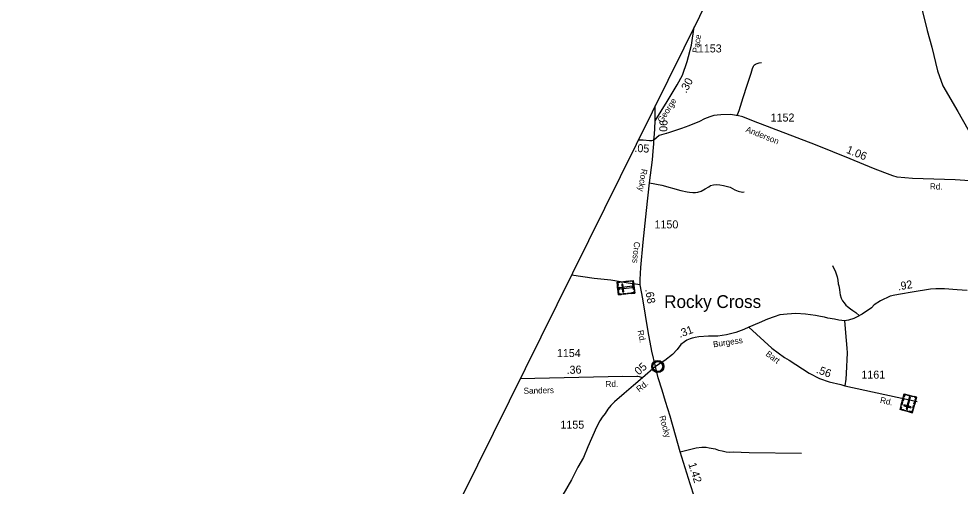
# Model space of a CAD drawing. Extents: x 2220236 to 2384410, y 720751 to 894131.
# Drawn here: x 2220576 to 2235281, y 768138 to 775435 of the extents above; entities that cross this region are included whole.
import ezdxf

# ---------------------------------------------------------------- set-up
doc = ezdxf.new("R2010")
doc.units = 0
doc.layers.add('Default', color=7, linetype='Continuous')

msp = doc.modelspace()

# ---------------------------------------------------------------- linework, layer by layer
at = {"layer": 'Default'}
for p, q in [((2230516, 773844), (2230516, 774074)), ((2230520, 770009), (2230316, 769832))]:
    msp.add_line(p, q, dxfattribs=at)
for points in [[(2293118, 894131), (2291904, 891776), (2258822, 829665), (2255410, 823324), (2242089, 797599), (2231460, 775981), (2225011, 762953), (2220576, 753519)], [(2234647, 775741), (2234764, 775250), (2234839, 774993), (2234924, 774625), (2235009, 774391), (2235244, 773990), (2235402, 773711), (2235753, 773038), (2235850, 772874)], [(2230516, 773844), (2230705, 774144), (2230862, 774403), (2230945, 774553), (2231016, 774771), (2231083, 775022), (2231127, 775308)], [(2231799, 773924), (2231829, 774005), (2231893, 774209), (2231955, 774397), (2232017, 774587), (2232036, 774659), (2232050, 774694), (2232059, 774707), (2232069, 774717), (2232085, 774725), (2232112, 774736), (2232139, 774746), (2232176, 774752)], [(2235432, 772907), (2235201, 772920), (2234535, 772942), (2234295, 772964), (2234227, 772985), (2234102, 773031), (2233926, 773099), (2233562, 773248), (2233021, 773465), (2232050, 773838), (2231887, 773906), (2231799, 773924), (2231782, 773928), (2231698, 773940), (2231542, 773937), (2231484, 773933), (2231430, 773923), (2231372, 773906), (2231288, 773874), (2231211, 773834), (2231043, 773763), (2230926, 773723), (2230832, 773692), (2230723, 773656), (2230579, 773614), (2230496, 773541)], [(2230496, 773541), (2230505, 773636), (2230512, 773720), (2230516, 773844)], [(2230496, 773541), (2230461, 773532), (2230427, 773532), (2230328, 773538), (2230251, 773540)], [(2230520, 770009), (2230466, 770246), (2230407, 770554), (2230321, 771064), (2230284, 771284), (2230284, 771363), (2230292, 771551), (2230331, 771947), (2230380, 772442), (2230425, 772876), (2230473, 773233), (2230484, 773370), (2230494, 773483), (2230496, 773541)], [(2230425, 772876), (2230620, 772839), (2230915, 772757), (2231016, 772735), (2231054, 772730), (2231102, 772724), (2231147, 772724), (2231185, 772728), (2231234, 772744), (2231296, 772780), (2231354, 772811), (2231381, 772832), (2231428, 772844), (2231482, 772846), (2231525, 772844), (2231586, 772834), (2231688, 772808), (2231763, 772763), (2231813, 772742), (2231880, 772730), (2231906, 772735)], [(2233288, 771583), (2233331, 771487), (2233360, 771409), (2233372, 771353), (2233376, 771297), (2233385, 771265), (2233395, 771210), (2233400, 771158), (2233406, 771124), (2233424, 771072), (2233443, 771034), (2233467, 771000), (2233497, 770965), (2233519, 770943), (2233566, 770905), (2233604, 770879), (2233652, 770852), (2233707, 770799)], [(2230284, 771284), (2230092, 771309), (2229822, 771353), (2229562, 771383), (2229208, 771432)], [(2235392, 771193), (2235234, 771204), (2235037, 771217), (2234899, 771218), (2234815, 771216), (2234532, 771166), (2234347, 771136), (2234259, 771119), (2234189, 771103), (2234035, 771034), (2233939, 770970), (2233894, 770925), (2233750, 770826), (2233673, 770782), (2233617, 770755), (2233537, 770730), (2233472, 770721), (2233432, 770725), (2233387, 770730), (2233316, 770744), (2233212, 770763), (2233160, 770775), (2233099, 770786), (2233023, 770803), (2232863, 770826), (2232714, 770832), (2232578, 770826), (2232465, 770812), (2232377, 770781), (2232270, 770744), (2232143, 770691), (2231978, 770620)], [(2233472, 770721), (2233498, 770411), (2233510, 770295), (2233513, 770220), (2233498, 769899), (2233493, 769811), (2233478, 769707)], [(2231978, 770620), (2231900, 770586), (2231777, 770537), (2231629, 770500), (2231494, 770479), (2231349, 770479), (2231196, 770468), (2231142, 770458), (2231120, 770454), (2231094, 770449), (2231061, 770439), (2231038, 770430), (2231010, 770416), (2230972, 770392), (2230917, 770348), (2230859, 770271), (2230785, 770196), (2230669, 770101), (2230520, 770009)], [(2231978, 770620), (2232099, 770513), (2232340, 770295), (2232534, 770145), (2232611, 770106), (2232922, 769904), (2233085, 769821), (2233234, 769766), (2233417, 769725), (2233478, 769707), (2234607, 769462)], [(2232001, 766033), (2231986, 766056), (2231957, 766104), (2231915, 766158), (2231869, 766209), (2231744, 766320), (2231622, 766441), (2231556, 766540), (2231515, 766658), (2231495, 766738), (2231447, 766978), (2231378, 767299), (2231337, 767427), (2231327, 767474), (2231206, 767744), (2231128, 767969), (2231063, 768174), (2230907, 768676), (2230835, 768936), (2230749, 769232), (2230675, 769462), (2230626, 769636), (2230564, 769829), (2230520, 770009)], [(2230316, 769832), (2230270, 769846), (2230013, 769850), (2228406, 769812)], [(2230316, 769832), (2230180, 769712), (2230034, 769585), (2229881, 769454), (2229826, 769399), (2229778, 769339), (2229737, 769275), (2229687, 769214), (2229654, 769158), (2229600, 769060), (2229463, 768753), (2229394, 768588), (2229310, 768434), (2229209, 768235), (2229075, 768002)], [(2230907, 768676), (2231158, 768736), (2231246, 768747), (2231314, 768748), (2231360, 768736), (2231452, 768721), (2231506, 768703), (2231563, 768688), (2231627, 768672), (2231677, 768671), (2231735, 768673), (2231987, 768665), (2232800, 768656)]]:
    msp.add_lwpolyline(points, dxfattribs=at)
for points in [[(2229944, 771124), (2229921, 771322), (2230174, 771351), (2230197, 771153)], [(2229964, 771327), (2229966, 771316), (2229934, 771312), (2229938, 771272), (2229927, 771271), (2229921, 771322)], [(2230007, 771173), (2230025, 771175), (2230012, 771292), (2229993, 771290)], [(2230038, 771324), (2229995, 771319), (2229994, 771331), (2230037, 771335)], [(2230104, 771332), (2230061, 771327), (2230059, 771338), (2230102, 771343)], [(2230178, 771318), (2230167, 771317), (2230164, 771339), (2230124, 771334), (2230123, 771345), (2230174, 771351)], [(2230179, 771209), (2230169, 771293), (2230181, 771295), (2230190, 771210)], [(2229935, 771198), (2229929, 771250), (2229941, 771251), (2229947, 771199)], [(2229987, 771129), (2229985, 771141), (2229953, 771137), (2229949, 771177), (2229938, 771176), (2229944, 771124)], [(2229960, 771236), (2229963, 771218), (2230164, 771240), (2230162, 771259)], [(2230060, 771138), (2230017, 771133), (2230016, 771144), (2230059, 771149)], [(2230127, 771145), (2230084, 771140), (2230083, 771152), (2230126, 771157)], [(2230193, 771186), (2230181, 771185), (2230184, 771163), (2230144, 771158), (2230145, 771147), (2230197, 771153)], [(2230480, 770019), (2230481, 770025), (2230483, 770031), (2230485, 770039), (2230488, 770044), (2230492, 770050), (2230495, 770055), (2230499, 770060), (2230504, 770064), (2230510, 770069), (2230515, 770072), (2230520, 770075), (2230525, 770078), (2230530, 770080), (2230536, 770082), (2230540, 770083), (2230545, 770084), (2230549, 770084), (2230556, 770085), (2230560, 770085), (2230566, 770084), (2230571, 770084), (2230576, 770083), (2230581, 770081), (2230586, 770079), (2230592, 770076), (2230599, 770073), (2230604, 770069), (2230609, 770065), (2230612, 770062), (2230616, 770058), (2230620, 770053), (2230623, 770049), (2230626, 770044), (2230629, 770038), (2230631, 770033), (2230632, 770028), (2230634, 770024), (2230635, 770018), (2230635, 770013), (2230636, 770007), (2230636, 770001), (2230635, 769996), (2230634, 769990), (2230632, 769984), (2230631, 769978), (2230628, 769973), (2230625, 769967), (2230622, 769962), (2230618, 769957), (2230614, 769952), (2230609, 769947), (2230604, 769943), (2230599, 769940), (2230594, 769937), (2230588, 769934), (2230581, 769931), (2230575, 769930), (2230568, 769928), (2230564, 769928), (2230559, 769928), (2230553, 769928), (2230549, 769928), (2230544, 769929), (2230538, 769930), (2230533, 769931), (2230528, 769933), (2230523, 769935), (2230519, 769938), (2230513, 769942), (2230507, 769946), (2230502, 769950), (2230498, 769955), (2230494, 769959), (2230491, 769963), (2230487, 769971), (2230486, 769974), (2230484, 769978), (2230481, 769986), (2230480, 769993), (2230479, 769998), (2230479, 770005), (2230479, 770010), (2230479, 770016)], [(2234533, 769283), (2234341, 769335), (2234407, 769581), (2234600, 769529)], [(2234439, 769572), (2234436, 769561), (2234415, 769567), (2234405, 769528), (2234394, 769531), (2234407, 769581)], [(2234436, 769340), (2234454, 769335), (2234506, 769531), (2234488, 769536)], [(2234541, 769533), (2234459, 769555), (2234462, 769566), (2234544, 769544)], [(2234568, 769538), (2234565, 769527), (2234586, 769521), (2234575, 769482), (2234586, 769479), (2234600, 769529)], [(2234352, 769377), (2234363, 769374), (2234355, 769343), (2234394, 769333), (2234391, 769322), (2234341, 769335)], [(2234382, 769445), (2234371, 769403), (2234360, 769406), (2234371, 769448)], [(2234400, 769508), (2234388, 769467), (2234377, 769470), (2234389, 769511)], [(2234512, 769360), (2234516, 769378), (2234403, 769408), (2234398, 769390)], [(2234564, 769397), (2234553, 769355), (2234542, 769358), (2234553, 769400)], [(2234581, 769462), (2234570, 769420), (2234559, 769423), (2234570, 769465)], [(2234462, 769303), (2234412, 769316), (2234415, 769327), (2234465, 769314)], [(2234545, 769325), (2234534, 769328), (2234525, 769297), (2234486, 769308), (2234483, 769297), (2234533, 769283)]]:
    msp.add_lwpolyline(points, close=True, dxfattribs=at)
for radius in [94.3, 76.7]:
    msp.add_circle((2230557, 770007), radius, dxfattribs=at)

# ---------------------------------------------------------------- texts
for s, height, rotation, p in [('Pace', 95, 80.4626, (2231189, 774897)), ('.30', 125, 61.0542, (2231001, 774266)), ('George', 95, 57.1506, (2230625, 773802)), ('.06', 125, 88.2643, (2230703, 773623)), ('Anderson', 95, 338.3571, (2231922, 773673)), ('.05', 125, 356.6625, (2230189, 773358)), ('1.06', 125, 337.7169, (2233491, 773346)), ('Rocky', 95, 261.2458, (2230302, 773097)), ('Rd.', 95, 358.892, (2234807, 772772)), ('Cross', 95, 265.1238, (2230187, 771957)), ('.92', 125, 9.4302, (2234315, 771194)), ('.68', 125, 279.5903, (2230360, 771209)), ('Rd.', 95, 281.5399, (2230240, 770565)), ('.31', 125, 20.4107, (2230903, 770453)), ('Burgess', 95, 8.5956, (2231428, 770305)), ('Bart', 95, 323.5418, (2232233, 770184)), ('.36', 125, 1.3541, (2229134, 769891)), ('.05', 125, 41.021, (2230224, 769834)), ('.56', 125, 339.5783, (2233022, 769911)), ('Sanders', 95, 1.399, (2228462, 769580)), ('Rd.', 95, 1.399, (2229742, 769685)), ('Rd.', 95, 39.553, (2230268, 769601)), ('Rd.', 95, 347.7724, (2234023, 769440)), ('Rocky', 95, 285.5566, (2230580, 769226)), ('1.42', 125, 287.5571, (2231032, 768486))]:
    msp.add_text(s, height=height, rotation=rotation, dxfattribs=at).set_placement(p)
for s, height, p in [('1153', 125, (2231183, 774910)), ('1152', 125, (2232320, 773831)), ('1150', 125, (2230506, 772163)), ('Rocky Cross', 200, (2230656, 770920)), ('1154', 125, (2228981, 770154)), ('1161', 125, (2233737, 769817)), ('1155', 125, (2229036, 769036))]:
    msp.add_text(s, height=height, dxfattribs=at).set_placement(p)

doc.saveas('drawing.dxf')
